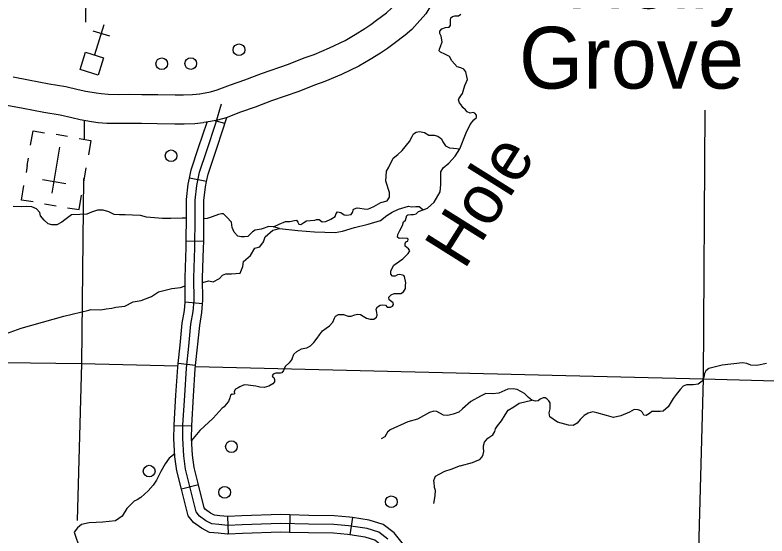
# Model space of a CAD drawing. Extents: x 1369979 to 1371646, y 379997 to 381064.
# Drawn here: x 1370664.4 to 1370739.8, y 380406.8 to 380459 of the extents above; entities that cross this region are included whole.
import ezdxf

# ---------------------------------------------------------------- set-up
doc = ezdxf.new("R2010")
doc.units = 0
doc.layers.add('R_Border Notes', color=7, linetype='Continuous')

msp = doc.modelspace()

# ---------------------------------------------------------------- linework, layer by layer
at = {"layer": 'R_Border Notes'}
for p, q in [((1370673.336, 380458.012), (1370672.408, 380454.997)), ((1370672.238, 380457.431), (1370673.918, 380456.914)), ((1370685.477, 380448.122), (1370684.494, 380448.409)), ((1370669.709, 380446.816), (1370668.553, 380447.009)), ((1370668.173, 380441.132), (1370668.945, 380445.756)), ((1370665.669, 380443.926), (1370665.551, 380443.214)), ((1370665.669, 380443.926), (1370665.792, 380444.659)), ((1370668.559, 380443.444), (1370668.559, 380443.444)), ((1370668.559, 380443.444), (1370668.559, 380443.444)), ((1370671.33, 380442.25), (1370671.571, 380443.695)), ((1370669.522, 380442.095), (1370667.2, 380442.483)), ((1370683.64, 380442.307), (1370681.914, 380442.639)), ((1370667.396, 380440.074), (1370668.552, 380439.881)), ((1370683.344, 380436.3), (1370681.586, 380436.315)), ((1370683.229, 380430.043), (1370681.479, 380430.202)), ((1370682.539, 380423.882), (1370680.792, 380424.07)), ((1370682.14, 380417.785), (1370680.382, 380417.819)), ((1370682.814, 380411.897), (1370681.108, 380411.471)), ((1370685.732, 380408.719), (1370685.811, 380406.963)), ((1370691.979, 380408.891), (1370691.93, 380407.134)), ((1370698.265, 380408.63), (1370698, 380406.892))]:
    msp.add_line(p, q, dxfattribs=at)
for points in [[(1370671.824, 380486.072), (1370671.497, 380458.298)], [(1370693.412, 380454.704), (1370694.409, 380455.054), (1370695.938, 380455.714), (1370697.508, 380456.463), (1370698.519, 380457.049), (1370699.488, 380457.655), (1370700.079, 380458.045), (1370700.669, 380458.487), (1370701.655, 380459.235), (1370702.152, 380459.679), (1370702.573, 380460.114), (1370703.221, 380460.864), (1370703.735, 380461.703), (1370704.397, 380462.921), (1370704.704, 380463.465), (1370704.971, 380464.113), (1370705.235, 380465.005), (1370705.627, 380466.694), (1370705.88, 380468.006), (1370706.082, 380468.833), (1370706.34, 380469.524), (1370706.71, 380470.601), (1370707.069, 380471.463)], [(1370709.773, 380470.337), (1370709.451, 380469.562), (1370709.098, 380468.534), (1370708.886, 380467.969), (1370708.743, 380467.381), (1370708.493, 380466.086), (1370708.069, 380464.256), (1370707.737, 380463.137), (1370707.345, 380462.183), (1370706.96, 380461.502), (1370706.273, 380460.237), (1370705.594, 380459.129), (1370704.735, 380458.136), (1370704.183, 380457.565), (1370703.518, 380456.972), (1370702.433, 380456.149), (1370701.767, 380455.648), (1370701.071, 380455.19), (1370700.031, 380454.539), (1370698.876, 380453.869), (1370697.149, 380453.046), (1370695.476, 380452.324), (1370694.442, 380451.961)], [(1370707.244, 380456.301), (1370707.14, 380456.869), (1370706.992, 380457.165), (1370706.992, 380457.373), (1370707.2, 380457.624), (1370707.555, 380457.758), (1370707.836, 380457.787), (1370707.939, 380457.787), (1370708.072, 380457.965), (1370708.087, 380458.246), (1370708.058, 380458.528), (1370708.117, 380458.735), (1370708.265, 380458.868), (1370708.516, 380458.913), (1370708.871, 380458.913), (1370709.108, 380459.09)], [(1370710.395, 380448.481), (1370710.691, 380448.719), (1370710.676, 380448.971), (1370710.513, 380449.178), (1370710.351, 380449.223), (1370710.04, 380449.178), (1370709.729, 380449.311), (1370709.567, 380449.504), (1370709.315, 380449.726), (1370709.123, 380450.007), (1370708.975, 380450.185), (1370708.871, 380450.511), (1370708.901, 380450.614), (1370709.093, 380450.911), (1370709.285, 380451.118), (1370709.507, 380451.947), (1370709.788, 380452.525), (1370709.715, 380452.85), (1370709.611, 380453.309), (1370709.419, 380453.576), (1370709.108, 380453.709), (1370708.753, 380453.798), (1370708.472, 380454.094), (1370708.22, 380454.405), (1370707.954, 380454.835), (1370707.495, 380455.086), (1370707.052, 380455.264), (1370706.948, 380455.427), (1370706.963, 380455.575), (1370707.066, 380455.856), (1370707.244, 380456.301)], [(1370682.91, 380451.109), (1370683.477, 380451.197), (1370684.022, 380451.316), (1370684.686, 380451.494), (1370686.017, 380452.007), (1370687.473, 380452.509), (1370689.124, 380453.154), (1370691.85, 380454.079), (1370693.412, 380454.704)], [(1370664.265, 380452.803), (1370665.806, 380452.498), (1370667.858, 380452.109), (1370669.548, 380451.822), (1370670.756, 380451.547), (1370671.529, 380451.381), (1370672.569, 380451.187), (1370673.086, 380451.119), (1370673.784, 380451.063), (1370674.829, 380451.048), (1370675.896, 380451.064), (1370677.154, 380451.048), (1370678.749, 380451.032), (1370680.5, 380450.985), (1370681.309, 380450.985), (1370682.226, 380451.028), (1370682.958, 380451.116)], [(1370694.442, 380451.961), (1370692.866, 380451.33), (1370690.129, 380450.401), (1370688.484, 380449.758), (1370687.021, 380449.254), (1370685.595, 380448.705), (1370684.715, 380448.469), (1370684.014, 380448.315), (1370683.356, 380448.214)], [(1370681.515, 380413.469), (1370681.341, 380414.811), (1370681.237, 380416.556), (1370681.263, 380417.885), (1370681.445, 380420.855), (1370681.627, 380423.616), (1370681.861, 380425.804), (1370682.069, 380428.006), (1370682.278, 380429.282), (1370682.382, 380430.428), (1370682.356, 380432.669), (1370682.46, 380435.665), (1370682.486, 380438.754), (1370682.486, 380440.448), (1370682.668, 380441.906), (1370682.928, 380443.261), (1370683.657, 380445.436), (1370684.568, 380448.146), (1370685.14, 380450.099)], [(1370683.308, 380448.207), (1370682.47, 380448.107), (1370681.378, 380448.055), (1370680.461, 380448.055), (1370678.696, 380448.103), (1370677.121, 380448.118), (1370675.899, 380448.134), (1370674.83, 380448.118), (1370673.647, 380448.135), (1370672.776, 380448.204), (1370672.109, 380448.293), (1370670.952, 380448.508), (1370670.123, 380448.687), (1370668.978, 380448.947), (1370667.34, 380449.225), (1370665.248, 380449.622), (1370663.619, 380449.945)], [(1370733.538, 380449.48), (1370733.401, 380422.539)], [(1370685.477, 380448.122), (1370685.654, 380448.728)], [(1370705.338, 380439.488), (1370705.765, 380439.64), (1370706.43, 380440.248), (1370707.037, 380441.284), (1370707.111, 380442.024), (1370707.111, 380442.883), (1370707.111, 380443.283), (1370707.347, 380443.668), (1370707.91, 380444.157), (1370708.546, 380444.838), (1370708.99, 380445.593), (1370709.626, 380447.207), (1370710.04, 380448.036), (1370710.395, 380448.481)], [(1370671.381, 380448.39), (1370671.358, 380446.486)], [(1370681.914, 380442.639), (1370682.076, 380443.485), (1370682.824, 380445.716), (1370683.68, 380448.264)], [(1370683.64, 380442.307), (1370683.78, 380443.038), (1370684.49, 380445.157), (1370685.406, 380447.882), (1370685.477, 380448.122)], [(1370666.007, 380445.949), (1370666.248, 380447.394), (1370667.404, 380447.201)], [(1370701.89, 380443.766), (1370702.334, 380444.649), (1370702.778, 380445.034), (1370703.236, 380445.433), (1370703.946, 380446.307), (1370704.242, 380446.84), (1370704.375, 380447.107), (1370704.627, 380447.255), (1370704.952, 380447.314), (1370705.455, 380447.21), (1370705.884, 380446.973), (1370706.432, 380446.944), (1370706.816, 380446.855), (1370707.157, 380446.603), (1370707.29, 380446.277), (1370707.556, 380445.892), (1370707.956, 380445.7), (1370708.355, 380445.641), (1370708.99, 380445.593)], [(1370670.871, 380446.622), (1370672.027, 380446.43), (1370671.786, 380444.985)], [(1370690.348, 380437.76), (1370690.898, 380438.021), (1370691.549, 380438.302), (1370691.978, 380438.302), (1370692.437, 380438.406), (1370692.644, 380438.435), (1370692.762, 380438.228), (1370692.88, 380438.05), (1370693.088, 380437.991), (1370693.383, 380438.198), (1370693.65, 380438.376), (1370694.034, 380438.406), (1370694.493, 380438.45), (1370694.656, 380438.509), (1370694.922, 380438.509), (1370695.203, 380438.272), (1370695.588, 380438.287), (1370696.091, 380438.539), (1370696.505, 380438.82), (1370696.608, 380439.102), (1370696.756, 380439.279), (1370697.082, 380439.19), (1370697.407, 380438.968), (1370697.674, 380438.954), (1370698.117, 380439.013), (1370698.251, 380439.22), (1370698.339, 380439.531), (1370698.724, 380439.664), (1370698.99, 380439.635), (1370699.419, 380439.575), (1370699.789, 380439.531), (1370700.396, 380439.798), (1370701.091, 380440.197), (1370701.727, 380440.39), (1370701.949, 380440.745), (1370701.949, 380441.219), (1370701.579, 380442.33), (1370701.653, 380443.337), (1370701.89, 380443.766)], [(1370671.313, 380442.621), (1370671.094, 380424.061)], [(1370681.586, 380436.315), (1370681.607, 380438.758), (1370681.607, 380440.502), (1370681.799, 380442.044), (1370681.914, 380442.639)], [(1370666.247, 380440.265), (1370665.091, 380440.458), (1370665.332, 380441.903)], [(1370683.344, 380436.3), (1370683.365, 380438.751), (1370683.365, 380440.393), (1370683.536, 380441.769), (1370683.64, 380442.307)], [(1370669.714, 380439.687), (1370670.87, 380439.494), (1370671.111, 380440.939)], [(1370679.223, 380438.589), (1370677.629, 380438.75), (1370677.022, 380438.899), (1370676.208, 380438.943), (1370675.483, 380438.973), (1370674.905, 380438.973), (1370674.373, 380439.017), (1370673.84, 380439.269), (1370673.263, 380439.432), (1370672.7, 380439.432), (1370672.108, 380439.254), (1370671.62, 380439.032), (1370670.939, 380439.017), (1370670.11, 380438.958), (1370669.429, 380438.484), (1370669.133, 380438.247), (1370668.63, 380437.98), (1370668.127, 380437.965), (1370667.757, 380438.069), (1370667.372, 380438.439), (1370666.987, 380438.884), (1370666.913, 380439.195), (1370666.588, 380439.565), (1370666.114, 380439.787), (1370665.566, 380439.802), (1370665.063, 380439.773), (1370664.249, 380439.817)], [(1370696.509, 380437.197), (1370697.256, 380437.339), (1370698.44, 380437.695), (1370699.831, 380438.021), (1370701.044, 380438.391), (1370701.695, 380438.909), (1370702.242, 380439.25), (1370702.849, 380439.546), (1370703.514, 380439.738), (1370703.869, 380439.827), (1370704.165, 380439.783), (1370704.609, 380439.798), (1370704.92, 380439.798), (1370705.068, 380439.709), (1370705.338, 380439.488)], [(1370703.41, 380432.874), (1370703.001, 380433.002), (1370702.749, 380432.958), (1370702.513, 380432.824), (1370702.276, 380432.81), (1370702.084, 380433.017), (1370702.084, 380433.357), (1370702.38, 380433.92), (1370703.282, 380434.572), (1370703.844, 380435.105), (1370704.007, 380435.371), (1370703.859, 380435.579), (1370703.534, 380435.816), (1370703.519, 380436.097), (1370703.593, 380436.275), (1370703.785, 380436.334), (1370703.815, 380436.526), (1370703.726, 380436.6), (1370703.238, 380436.63), (1370702.927, 380436.586), (1370702.749, 380436.748), (1370702.794, 380437.015), (1370703.001, 380437.4), (1370703.267, 380437.918), (1370703.371, 380438.259), (1370703.548, 380438.436), (1370703.682, 380438.896), (1370703.8, 380438.97), (1370704.081, 380438.999), (1370704.347, 380439.014), (1370704.643, 380439.088), (1370704.88, 380439.31), (1370705.338, 380439.488)], [(1370690.947, 380437.612), (1370690.348, 380437.76), (1370689.86, 380437.789), (1370689.105, 380437.523), (1370688.484, 380437.449), (1370688.235, 380437.265), (1370687.774, 380436.812), (1370687.433, 380436.753), (1370687.108, 380436.753), (1370686.768, 380436.842), (1370686.383, 380437.241), (1370686.191, 380437.715), (1370686.117, 380438.234), (1370685.658, 380438.752), (1370685.333, 380439.063), (1370685.14, 380439.078), (1370684.83, 380438.989), (1370684.548, 380438.9), (1370684.105, 380438.722), (1370683.69, 380438.589), (1370683.365, 380438.572)], [(1370681.607, 380438.622), (1370681.175, 380438.648), (1370680.051, 380438.604), (1370679.223, 380438.589)], [(1370683.24, 380432.189), (1370683.846, 380432.34), (1370684.29, 380432.251), (1370684.911, 380432.577), (1370685.236, 380432.932), (1370685.562, 380433.051), (1370686.124, 380433.051), (1370686.982, 380433.14), (1370687.278, 380433.791), (1370687.337, 380434.295), (1370688.047, 380434.887), (1370688.461, 380435.627), (1370688.964, 380435.776), (1370689.32, 380436.279), (1370689.497, 380436.753), (1370690.266, 380437.434), (1370690.947, 380437.612), (1370692.781, 380437.404), (1370694.438, 380437.256), (1370696.509, 380437.197)], [(1370681.479, 380430.202), (1370681.502, 380430.463), (1370681.477, 380432.679), (1370681.581, 380435.684), (1370681.586, 380436.315)], [(1370683.229, 380430.043), (1370683.261, 380430.394), (1370683.235, 380432.659), (1370683.339, 380435.646), (1370683.344, 380436.3)], [(1370702.325, 380430.157), (1370701.936, 380430.463), (1370701.891, 380430.714), (1370702.113, 380430.936), (1370702.424, 380431.084), (1370702.735, 380431.099), (1370703.105, 380431.084), (1370703.356, 380431.247), (1370703.548, 380431.588), (1370703.578, 380431.914), (1370703.608, 380432.165), (1370703.474, 380432.802), (1370703.41, 380432.874)], [(1370672.045, 380429.478), (1370673.046, 380429.438), (1370673.579, 380429.556), (1370674.141, 380429.616), (1370674.526, 380429.704), (1370675.443, 380429.823), (1370676.271, 380430.237), (1370677.07, 380430.386), (1370678.106, 380430.771), (1370678.816, 380431.244), (1370680.147, 380431.6), (1370681.035, 380431.689), (1370681.486, 380431.855)], [(1370680.792, 380424.07), (1370680.987, 380425.892), (1370681.197, 380428.118), (1370681.405, 380429.393), (1370681.479, 380430.202)], [(1370682.539, 380423.882), (1370682.736, 380425.716), (1370682.942, 380427.893), (1370683.15, 380429.171), (1370683.229, 380430.043)], [(1370692.206, 380424.534), (1370692.369, 380424.99), (1370692.679, 380425.286), (1370693.138, 380425.552), (1370693.463, 380425.612), (1370693.685, 380425.626), (1370694.04, 380425.834), (1370694.366, 380426.159), (1370694.721, 380426.618), (1370694.958, 380426.929), (1370695.239, 380427.359), (1370695.608, 380427.596), (1370695.934, 380427.847), (1370696.274, 380428.218), (1370696.452, 380428.617), (1370696.555, 380428.825), (1370696.851, 380428.973), (1370697.354, 380428.988), (1370697.828, 380428.825), (1370698.109, 380428.825), (1370698.493, 380428.943), (1370698.76, 380429.017), (1370699.07, 380428.988), (1370699.337, 380428.825), (1370699.647, 380428.603), (1370700.017, 380428.499), (1370700.387, 380428.499), (1370700.653, 380428.706), (1370700.712, 380428.928), (1370700.683, 380429.195), (1370700.638, 380429.521), (1370700.757, 380429.758), (1370701.008, 380429.921), (1370701.304, 380429.935), (1370701.556, 380429.906), (1370701.718, 380429.728), (1370702.073, 380429.713), (1370702.251, 380429.817), (1370702.355, 380429.98), (1370702.325, 380430.157)], [(1370659.93, 380425.437), (1370661.72, 380426.399), (1370665.063, 380427.613), (1370669.324, 380428.798), (1370671.839, 380429.42), (1370672.045, 380429.478)], [(1370635.265, 380424.547), (1370671.094, 380424.061)], [(1370692.206, 380424.534), (1370691.896, 380424.149), (1370691.511, 380423.764), (1370691.407, 380423.527), (1370691.348, 380423.364), (1370691.171, 380423.127), (1370691.038, 380423.083), (1370690.579, 380423.098), (1370690.313, 380422.994), (1370690.209, 380422.846), (1370690.224, 380422.757), (1370690.372, 380422.653), (1370690.446, 380422.461), (1370690.446, 380422.224), (1370690.283, 380422.017), (1370689.869, 380421.795)], [(1370671.094, 380424.061), (1370670.657, 380408.342)], [(1370671.094, 380424.061), (1370680.76, 380423.824)], [(1370680.382, 380417.819), (1370680.384, 380417.92), (1370680.568, 380420.91), (1370680.751, 380423.692), (1370680.792, 380424.07)], [(1370682.14, 380417.785), (1370682.141, 380417.849), (1370682.322, 380420.799), (1370682.503, 380423.54), (1370682.539, 380423.882)], [(1370682.519, 380423.781), (1370733.401, 380422.539)], [(1370739.723, 380424.075), (1370738.747, 380423.853), (1370738.17, 380423.912), (1370737.756, 380424.06), (1370737.341, 380424.149), (1370735.285, 380423.912), (1370733.968, 380423.572), (1370733.643, 380423.32), (1370733.51, 380423.068), (1370733.465, 380422.698), (1370733.273, 380422.313), (1370732.888, 380422.002), (1370732.371, 380421.928), (1370731.72, 380421.913), (1370731.365, 380421.795), (1370731.084, 380421.454)], [(1370733.401, 380422.539), (1370732.765, 380399.324)], [(1370733.401, 380422.539), (1370795.079, 380420.815)], [(1370689.869, 380421.795), (1370689.395, 380421.661), (1370688.952, 380421.706), (1370688.567, 380421.809), (1370688.02, 380421.869), (1370687.798, 380421.898), (1370687.398, 380421.913), (1370686.969, 380421.735), (1370686.792, 380421.617), (1370686.525, 380421.484), (1370686.407, 380421.262), (1370686.422, 380421.039)], [(1370718.071, 380419.52), (1370718.059, 380420.128), (1370717.926, 380420.335), (1370717.733, 380420.542), (1370717.571, 380420.631), (1370717.349, 380420.616), (1370717.053, 380420.483), (1370716.846, 380420.335), (1370716.579, 380420.305), (1370716.21, 380420.394), (1370715.899, 380420.646), (1370715.485, 380421.06), (1370714.76, 380421.445), (1370714.346, 380421.519), (1370713.813, 380421.49), (1370712.913, 380421.094), (1370712.263, 380421.035)], [(1370731.084, 380421.454), (1370730.674, 380420.957), (1370730.378, 380420.572), (1370730.082, 380420.053), (1370729.89, 380419.728), (1370729.372, 380419.283), (1370729.091, 380419.254), (1370728.603, 380419.269), (1370728.41, 380419.269), (1370728.233, 380419.254), (1370728.011, 380419.047), (1370727.685, 380418.839), (1370727.434, 380418.884), (1370727.301, 380419.15), (1370727.123, 380419.313), (1370726.872, 380419.432), (1370726.487, 380419.461), (1370725.999, 380419.18)], [(1370686.422, 380421.039), (1370686.29, 380420.965), (1370686.187, 380420.98), (1370686.039, 380420.906), (1370685.95, 380420.64), (1370685.817, 380420.255), (1370685.58, 380420.003), (1370685.388, 380419.736), (1370685.181, 380419.584)], [(1370712.263, 380421.035), (1370711.626, 380421.065), (1370711.079, 380420.798), (1370710.117, 380420.25), (1370709.289, 380419.525), (1370708.904, 380419.199), (1370708.327, 380418.992), (1370707.81, 380418.858), (1370707.381, 380418.873), (1370706.715, 380419.258), (1370706.404, 380419.288), (1370705.96, 380419.155), (1370704.762, 380418.503), (1370703.8, 380418.207), (1370702.01, 380417.407)], [(1370709.052, 380413.8), (1370710.265, 380414.156), (1370710.754, 380414.333), (1370711.005, 380414.437), (1370711.257, 380414.718), (1370711.345, 380414.94), (1370711.404, 380415.251), (1370711.36, 380415.607), (1370711.375, 380415.829), (1370711.478, 380416.184), (1370711.804, 380416.584), (1370712.307, 380416.925), (1370712.499, 380417.265), (1370712.588, 380417.532), (1370712.795, 380417.828), (1370713.195, 380418.316), (1370713.535, 380418.918), (1370713.845, 380419.392), (1370714.408, 380419.717), (1370714.955, 380420.087), (1370716.21, 380420.394)], [(1370685.181, 380419.584), (1370684.293, 380418.596), (1370682.962, 380417.367), (1370682.129, 380416.362)], [(1370725.999, 380419.18), (1370725.142, 380418.81), (1370724.388, 380418.662), (1370723.707, 380418.869), (1370722.746, 380419.135), (1370722.346, 380419.209), (1370721.858, 380419.091), (1370721.459, 380418.869), (1370721.059, 380418.469), (1370720.748, 380418.084), (1370720.349, 380417.862), (1370719.876, 380417.877), (1370718.796, 380418.203), (1370718.026, 380418.736), (1370717.952, 380419.121), (1370718.071, 380419.52)], [(1370681.108, 380411.471), (1370680.65, 380413.305), (1370680.465, 380414.728), (1370680.357, 380416.539), (1370680.382, 380417.819)], [(1370682.814, 380411.897), (1370682.38, 380413.633), (1370682.216, 380414.894), (1370682.116, 380416.574), (1370682.14, 380417.785)], [(1370702.01, 380417.407), (1370701.747, 380417.185), (1370701.481, 380416.726), (1370701.14, 380416.519)], [(1370680.449, 380415.002), (1370679.887, 380414.591), (1370679.488, 380413.998), (1370679.044, 380413.243), (1370678.63, 380412.369), (1370678.29, 380411.866), (1370677.772, 380411.289), (1370677.062, 380410.622), (1370676.692, 380410.4), (1370676.366, 380410.252), (1370675.641, 380409.541)], [(1370709.052, 380413.8), (1370708.108, 380413.448), (1370707.472, 380413.226), (1370706.895, 380412.929), (1370706.54, 380412.737), (1370706.466, 380412.589), (1370706.363, 380412.322), (1370706.392, 380412.145), (1370706.422, 380411.656), (1370706.525, 380411.375), (1370706.496, 380410.812), (1370706.377, 380410.027)], [(1370701.789, 380406.448), (1370700.904, 380407.152), (1370699.733, 380407.517), (1370697.859, 380407.803), (1370696.375, 380407.933), (1370693.851, 380407.959), (1370691.066, 380408.038), (1370687.212, 380407.905), (1370685.755, 380407.84), (1370684.872, 380407.92), (1370684.17, 380407.998), (1370683.571, 380408.311), (1370682.92, 380408.78), (1370682.582, 380409.197), (1370681.515, 380413.469)], [(1370685.775, 380408.721), (1370684.961, 380408.795), (1370684.43, 380408.854), (1370684.034, 380409.061), (1370683.529, 380409.425), (1370683.387, 380409.599), (1370682.814, 380411.897)], [(1370685.81, 380406.963), (1370685.735, 380406.96), (1370684.784, 380407.046), (1370683.909, 380407.143), (1370683.108, 380407.561), (1370682.312, 380408.135), (1370681.777, 380408.794), (1370681.108, 380411.471)], [(1370675.641, 380409.541), (1370675.181, 380408.775), (1370674.5, 380408.286), (1370673.243, 380408.153), (1370672.577, 380408.138), (1370671.882, 380408.094), (1370671.098, 380407.916), (1370670.684, 380407.59), (1370670.373, 380407.161), (1370670.536, 380406.672), (1370670.758, 380406.006), (1370670.787, 380405.576), (1370670.772, 380405.088), (1370670.373, 380404.584), (1370669.485, 380404.199), (1370668.45, 380404.081), (1370667.414, 380404.096)], [(1370691.979, 380408.891), (1370691.064, 380408.917), (1370687.178, 380408.784), (1370685.732, 380408.719)], [(1370698.265, 380408.63), (1370697.964, 380408.676), (1370696.418, 380408.812), (1370693.868, 380408.838), (1370691.979, 380408.891)], [(1370703.889, 380405.245), (1370703.76, 380405.422), (1370702.41, 380407.077), (1370701.322, 380407.942), (1370699.931, 380408.375), (1370698.265, 380408.63)], [(1370691.93, 380407.134), (1370691.069, 380407.158), (1370687.247, 380407.027), (1370685.811, 380406.963)], [(1370698, 380406.892), (1370697.754, 380406.93), (1370696.332, 380407.055), (1370693.834, 380407.081), (1370691.93, 380407.134)], [(1370702.467, 380404.211), (1370702.367, 380404.349), (1370701.167, 380405.819), (1370700.485, 380406.362), (1370699.534, 380406.658), (1370698, 380406.892)]]:
    msp.add_lwpolyline(points, dxfattribs=at)
msp.add_lwpolyline([(1370670.96, 380453.529), (1370671.498, 380455.277), (1370673.311, 380454.719), (1370672.773, 380452.971)], close=True, dxfattribs=at)
for centre in [(1370686.877, 380455.517), (1370679.139, 380454.112), (1370682.045, 380454.134), (1370680.077, 380444.889), (1370686.125, 380415.732), (1370677.88, 380413.278), (1370685.445, 380411.158), (1370702.138, 380410.207)]:
    msp.add_circle(centre, 0.586, dxfattribs=at)

# ---------------------------------------------------------------- texts
for s, p in [('Holly', (1370719.665, 380459.669)), ('Grove', (1370714.935, 380451.629))]:
    msp.add_text(s, height=6.1875, dxfattribs=at).set_placement(p)
msp.add_text('Hole', height=4.95, rotation=57.87346, dxfattribs=at).set_placement((1370709.448, 380433.365))

doc.saveas('drawing.dxf')
